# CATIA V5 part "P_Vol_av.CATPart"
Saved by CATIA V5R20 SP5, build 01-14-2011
Part number: Vol_av
Bounding box of the stored display mesh (mm): x -43.683 to 43.683, y 330 to 450, z -1030 to -10
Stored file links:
  U:\2A\CFAO\dossier sans titre\P_Vol_av.CATPart
  U:\2A\CFAO\dossier sans titre\Gouvernail.CATProduct
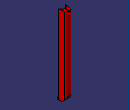
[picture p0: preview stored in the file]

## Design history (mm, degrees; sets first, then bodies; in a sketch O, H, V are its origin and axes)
External parameters (linked from other documents)
  External.Larg_Totale = 450 mm
Set1
  Point1 to Point3: linked copy from another document
Set2
  Plane1: type OffsetPt, RefPlane xy-plane, RefPoint Point3
  Plane2: type OffsetPt, RefPlane zx-plane, RefPoint Point1
Body1 (main body)
  Sketch1 "Esquisse_trans" on xy-plane, origin (0, 0, 0), H (1, 0, 0), V (0, 1, 0)
    construction line L1 (0, 555.4217) -> (0, -60.5461)
    point P1 (0, 555.4217)
    construction arc A1 centre (0, 415) radius 35 from (-34.4998, 420.8959) to (34.4998, 420.8959) cw
    point P3 (0, 415)
    point P4 (-34.4998, 420.8959)
    reference projected point E1 (0, 450) from Point1
    construction arc A2 centre (-803.3534, 277.7108) radius 850 from (34.4998, 420.8959) to (0, 0) cw
    construction arc A3 centre (803.3534, 277.7108) radius 850 from (-34.4998, 420.8959) to (0, 0) ccw
    point P8 (0, 0)
    arc A4 centre (0, 346.2739) radius 43.7261 from (43.5677, 349.9922) to (-43.5677, 349.9922) ccw
    point P9 (0, 346.2739)
    point P10 (43.5677, 349.9922)
    point P11 (-43.5677, 349.9922)
    reference projected point E2 (0, 390) from Point2
    arc A5 centre (803.3534, 277.7108) radius 850 from (-43.5677, 349.9922) to (-34.4998, 420.8959) cw
    point P13 (-34.4998, 420.8959)
    arc A6 centre (-803.3534, 277.7108) radius 850 from (43.5677, 349.9922) to (34.4998, 420.8959) ccw
    point P15 (43.5677, 349.9922)
    point P16 (34.4998, 420.8959)
    arc A7 centre (0, 415) radius 35 from (-34.4998, 420.8959) to (34.4998, 420.8959) cw
    point P18 (34.4998, 420.8959)
    point P19 (-34.4998, 420.8959)
    point P20 (34.4998, 420.8959)
    radius A2 = 850 {= (850/450)*External.Larg_Totale}
    radius A3 = 850 {= (850/450)*External.Larg_Totale}
    radius A1 = 35 {= (35/450)*External.Larg_Totale}
    coincidence: L1 V, P3 L1, A1 E1, A2 P1, P8 A2, P8 L1, P11 A3, P9 L1, P10 A2, A4 E2, P13 A3, A5 A3, P15 P10, A6 A2, A7 P18, P18 A2, P19 P4, P20 P16, A7 A1, P13 P4
    tangency: A1 A2, A3 A1, A4 A5
  Sketch2 "Esquisse_long" on yz-plane, origin (0, 0, 0), H (0, 1, 0), V (0, 0, 1)
    line L1 (300, -1010) -> (392, -1010)
    line L2 (450, -910.5786) -> (450, 0)
    point P2 (450, 0)
    reference projected point E1 (450, -10) from Point1
    line L3 (300, -1010) -> (300, 0)
    line L4 (300, 0) -> (450, 0)
    point P4 (450, 0)
    reference projected point E2 (360, -1010) from Point3
    line L5 (420.7107, -981.2893) -> (392, -1010)
    point P5 (450, -952)
    arc A1 centre (350, -910.5786) radius 100 from (420.7107, -981.2893) to (450, -910.5786) ccw
    length L4 = 150 {= (150/450)*External.Larg_Totale}
    angle L2 L5 = 45
    radius A1 = 100 {= (100/450)*External.Larg_Totale}
    length L1 = 92 {= (92/450)*External.Larg_Totale}
    horizontal: L1 H, L4 H
    vertical: L2 V, L3 V
    coincidence: L2 E1, P4 P2, L4 H, L1 E2, L5 P5, L2 P5
    tangency: A1 L5, A1 L2
  SolidCombine1: FirstComponentDirection Sketch1, FirstComponentProfile Sketch1, SecondComponentDirection Sketch2, SecondComponentProfile Sketch2
  Sketch3 on Plane1, origin (0, 0, -1010), H (1, 0, 0), V (0, 1, 0)
    construction line L1 (0, 487.0293) -> (0, -62.8334)
    construction arc A1 centre (0, 415) radius 35 from (-34.4998, 420.8959) to (34.4998, 420.8959) cw
    point P3 (0, 415)
    point P4 (0, 450)
    point P6 (34.4998, 420.8959)
    construction arc A2 centre (-803.3534, 277.7108) radius 850 from (34.4998, 420.8959) to (0, 0) cw
    point P8 (34.4998, 420.8959)
    construction arc A3 centre (803.3534, 277.7108) radius 850 from (-34.4998, 420.8959) to (0, 0) ccw
    point P10 (0, 0)
    reference projected point E1 (0, 450) from Point1
    arc A4 centre (0, 346.2739) radius 43.7261 from (43.5677, 349.9922) to (-43.5677, 349.9922) ccw
    point P11 (0, 346.2739)
    point P12 (43.5677, 349.9922)
    point P13 (-43.5677, 349.9922)
    reference projected point E2 (0, 390) from Point2
    arc A5 centre (-803.3534, 277.7108) radius 850 from (43.5677, 349.9922) to (43.6784, 348.683) cw
    point P15 (44.3612, 340)
    arc A6 centre (803.3534, 277.7108) radius 850 from (-43.5677, 349.9922) to (-43.6784, 348.683) ccw
    point P17 (-44.3612, 340)
    axis line L2 (125.1727, 340) -> (-118.6781, 340)
    point P20 (0, 292.5426)
    arc A7 centre (0, 433.3958) radius 103.3958 from (35.8851, 336.427) to (-35.8851, 336.427) cw
    arc A8 centre (31.7203, 347.6811) radius 12 from (35.8851, 336.427) to (43.6784, 348.683) ccw
    arc A9 centre (-31.7203, 347.6811) radius 12 from (-35.8851, 336.427) to (-43.6784, 348.683) cw
    radius A2 = 850 {= (850/450)*External.Larg_Totale}
    radius A3 = 850 {= (850/450)*External.Larg_Totale}
    radius A1 = 35 {= (35/450)*External.Larg_Totale}
    distance L2 A4 = 50 {= (50/450)*External.Larg_Totale}
    radius A8 = 12
    radius A9 = 12
    distance A7 L2 = 10 {= (10/450)*External.Larg_Totale}
    vertical: L1 V
    coincidence: L1 V, A1 P4, P4 V, P8 A1, P10 A2, P10 H, P8 P6, A1 E1, P3 L1, E2 A4, P11 L1, P12 A2, P13 A3, P15 A2, A5 A2, P17 A3, A6 A3, P15 L2, P17 L2, P20 L1, A7 P15, A5 P15, A7 P17, A6 P17
    tangency: A2 A1, A3 A1, A4 A6, A8 A7, A8 A5, A9 A7, A9 A6
    perpendicularity: L2 L1
  Pad1 "Extrusion_liaison_gouv": profile Sketch3, direction (0, 0, 1), length 20
  Sketch4 on Plane1, origin (0, 0, -1010), H (1, 0, 0), V (0, 1, 0)
    circle A1 centre (0, 360) radius 8
    point P1 (0, 360)
    reference projected point E1 (0, 360) from Point3
    radius A1 = 8
    coincidence: P1 E1
  Pad2 "Extrusion_liaison_gouv_2": profile Sketch4, direction (0, 0, -1), length 20
  Fillet1 "Congé_liaison_gouv_2": radius 3, on face of Pad2 from Sketch4.A1
  Sketch5 on xy-plane, origin (0, 0, 0), H (1, 0, 0), V (0, 1, 0)
    line L1 (-75, 470) -> (75, 470)
    line L2 (75, 470) -> (75, 320)
    line L3 (75, 320) -> (-75, 320)
    line L4 (-75, 320) -> (-75, 470)
    length L3 = 150 {= (150/450)*External.Larg_Totale}
    length L2 = 150 {= Sketch5.length(L3)}
    distance L3 H = 320 {= (320/450)*External.Larg_Totale}
    distance L2 V = 75 {= Sketch5.length(L3) /2}
    horizontal: L1 H, L3 H
    vertical: L2 V, L4 V
  Pocket1 "Poche_10mm": profile Sketch5, direction (0, 0, -1), length 10
  Sketch6 on Plane2, origin (0, 450, 0), H (-1, 0, 0), V (0, 0, 1)
    line L1 (5, -23) -> (-5, -23)
    line L2 (-5, -23) -> (-5, -13)
    line L3 (-5, -13) -> (-3, -13)
    line L4 (-3, -13) -> (-3, -10)
    line L5 (-3, -10) -> (3, -10)
    line L6 (3, -10) -> (3, -13)
    point P7 (3, -13)
    line L7 (3, -13) -> (5, -13)
    line L8 (5, -13) -> (5, -23)
    length L1 = 10
    length L5 = 6
    length L8 = 10
    length L6 = 3
    distance L4 L2 = 2
    distance L8 V = 5
    distance L5 H = 10
    horizontal: L1 H, L3 H, L5 H, L7 H
    vertical: L2 V, L4 V, L6 V, L8 V
    coincidence: P7 L3
  Pocket2 "Poche_bras_av": profile Sketch6, direction (0, -1, 0), through (limit type 3)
